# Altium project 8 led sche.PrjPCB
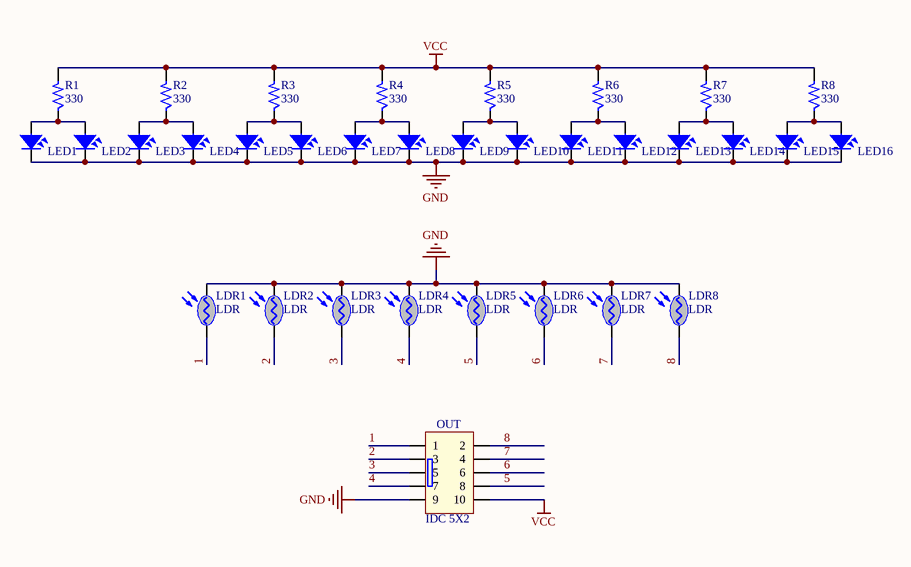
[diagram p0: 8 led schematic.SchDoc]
1 sheet, 33 parts. Net scope: global (net labels, ports and power ports of the same name join across sheets).
Board file: 8 sensor PCB.PcbDoc

## Sheet 8 led schematic.SchDoc
size A4

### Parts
LDR1  LDR  [CDS]
LDR2  LDR  [CDS]
LDR3  LDR  [CDS]
LDR4  LDR  [CDS]
LDR5  LDR  [CDS]
LDR6  LDR  [CDS]
LDR7  LDR  [CDS]
LDR8  LDR  [CDS]
LED1  LED  [LED-5-RED]  (value not drawn)
LED2  LED  [LED-5-RED]  (value not drawn)
LED3  LED  [LED-5-RED]  (value not drawn)
LED4  LED  [LED-5-RED]  (value not drawn)
LED5  LED  [LED-5-RED]  (value not drawn)
LED6  LED  [LED-5-RED]  (value not drawn)
LED7  LED  [LED-5-RED]  (value not drawn)
LED8  LED  [LED-5-RED]  (value not drawn)
LED9  LED  [LED-5-RED]  (value not drawn)
LED10  LED  [LED-5-RED]  (value not drawn)
LED11  LED  [LED-5-RED]  (value not drawn)
LED12  LED  [LED-5-RED]  (value not drawn)
LED13  LED  [LED-5-RED]  (value not drawn)
LED14  LED  [LED-5-RED]  (value not drawn)
LED15  LED  [LED-5-RED]  (value not drawn)
LED16  LED  [LED-5-RED]  (value not drawn)
OUT  IDC 5X2  [IDC10-BH]
R1  330  [R1/4W]
R2  330  [R1/4W]
R3  330  [R1/4W]
R4  330  [R1/4W]
R5  330  [R1/4W]
R6  330  [R1/4W]
R7  330  [R1/4W]
R8  330  [R1/4W]

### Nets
GND: LDR1.2(K) LDR2.2(K) LDR3.2(K) LDR4.2(K) LDR5.2(K) LDR6.2(K) LDR7.2(K) LDR8.2(K) LED1.2 LED2.2 LED3.2 LED4.2 LED5.2 LED6.2 LED7.2 LED8.2 LED9.2 LED10.2 LED11.2 LED12.2 LED13.2 LED14.2 LED15.2 LED16.2 OUT.9
VCC: OUT.10 R1.2 R2.2 R3.2 R4.2 R5.2 R6.2 R7.2 R8.2
1: LDR1.1(A) OUT.1
2: LDR2.1(A) OUT.3
3: LDR3.1(A) OUT.5
4: LDR4.1(A) OUT.7
5: LDR5.1(A) OUT.8
6: LDR6.1(A) OUT.6
7: LDR7.1(A) OUT.4
8: LDR8.1(A) OUT.2
NetLED1_1: LED1.1 LED2.1 R1.1
NetLED3_1: LED3.1 LED4.1 R2.1
NetLED5_1: LED5.1 LED6.1 R3.1
NetLED7_1: LED7.1 LED8.1 R4.1
NetLED9_1: LED9.1 LED10.1 R5.1
NetLED11_1: LED11.1 LED12.1 R6.1
NetLED13_1: LED13.1 LED14.1 R7.1
NetLED15_1: LED15.1 LED16.1 R8.1

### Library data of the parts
LDR1-LDR8 = LDR: Quang Tro
LED1-LED16 = LED: LED Single colour Green and Red; Value: LED 3 ly Single Colour
OUT = IDC 5X2: Header, 5X2-Pin; Value: Header 5x2
R1-R8 = R: Resistor 1/4W; Value: R1/4W - 1K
